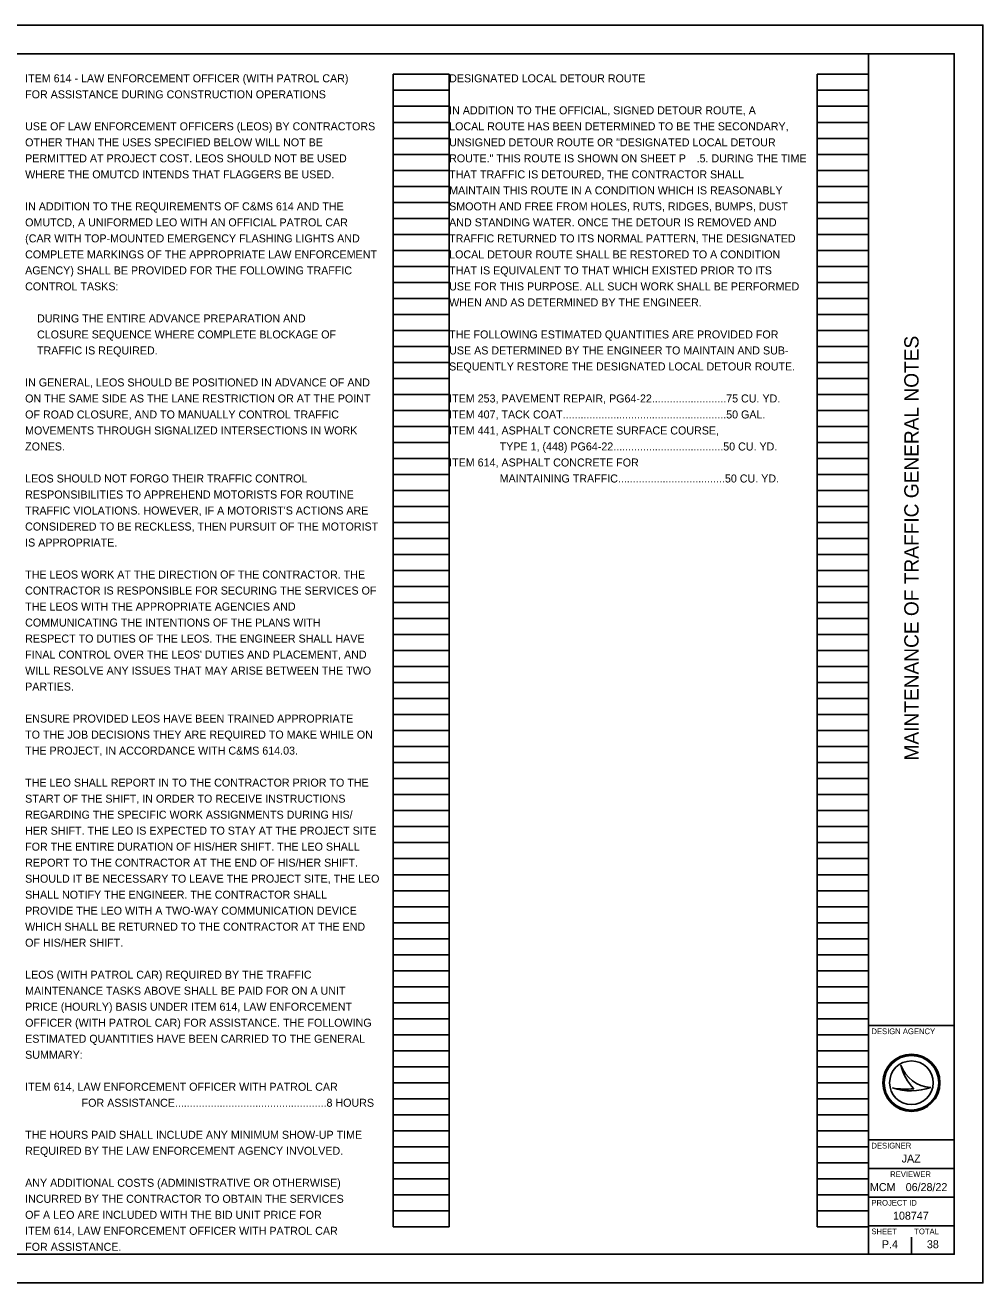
# Model space of a CAD drawing. Extents: x 0 to 34, y 0 to 22.
# Drawn here: x 17.24 to 34, y 0 to 22 of the extents above; entities that cross this region are included whole.
import ezdxf

# ---------------------------------------------------------------- set-up
doc = ezdxf.new("R2010")
doc.units = 0
for name, color, linetype in [('SH_Border', 7, 'Continuous'), ('SH_Cut_Line', 7, 'Continuous'), ('SH_Data', 7, 'Continuous'), ('SH_Text', 7, 'Continuous')]:
    doc.layers.add(name, color=color, linetype=linetype)

msp = doc.modelspace()

# ---------------------------------------------------------------- linework, layer by layer
at = {"layer": 'SH_Border'}
for p, q in [((32, 0.5), (32, 21.5)), ((32, 4.5), (33.5, 4.5)), ((32, 2.5), (33.5, 2.5)), ((32, 2), (33.5, 2)), ((32, 1.5), (33.5, 1.5)), ((32, 1), (33.5, 1))]:
    msp.add_line(p, q, dxfattribs=at)
msp.add_lwpolyline([(1.5, 21.5), (33.5, 21.5), (33.5, 0.5), (1.5, 0.5)], close=True, dxfattribs=at)
at = {"layer": 'SH_Cut_Line'}
msp.add_lwpolyline([(0, 0), (34, 0), (34, 22), (0, 22)], close=True, dxfattribs=at)
at = {"layer": 'SH_Data'}
for p, q in [((23.68, 0.98), (23.68, 21.14)), ((23.68, 21.14), (24.66, 21.14)), ((24.66, 0.98), (24.66, 21.14)), ((31.1, 0.98), (31.1, 21.14)), ((31.1, 21.14), (32, 21.14)), ((32, 0.98), (32, 21.14)), ((23.68, 20.86), (24.66, 20.86)), ((31.1, 20.86), (32, 20.86)), ((23.68, 20.58), (24.66, 20.58)), ((31.1, 20.58), (32, 20.58)), ((23.68, 20.3), (24.66, 20.3)), ((31.1, 20.3), (32, 20.3)), ((23.68, 20.02), (24.66, 20.02)), ((31.1, 20.02), (32, 20.02)), ((23.68, 19.74), (24.66, 19.74)), ((31.1, 19.74), (32, 19.74)), ((23.68, 19.46), (24.66, 19.46)), ((31.1, 19.46), (32, 19.46)), ((23.68, 19.18), (24.66, 19.18)), ((31.1, 19.18), (32, 19.18)), ((23.68, 18.9), (24.66, 18.9)), ((31.1, 18.9), (32, 18.9)), ((23.68, 18.62), (24.66, 18.62)), ((31.1, 18.62), (32, 18.62)), ((23.68, 18.34), (24.66, 18.34)), ((31.1, 18.34), (32, 18.34)), ((23.68, 18.06), (24.66, 18.06)), ((31.1, 18.06), (32, 18.06)), ((23.68, 17.78), (24.66, 17.78)), ((31.1, 17.78), (32, 17.78)), ((23.68, 17.5), (24.66, 17.5)), ((31.1, 17.5), (32, 17.5)), ((23.68, 17.22), (24.66, 17.22)), ((31.1, 17.22), (32, 17.22)), ((23.68, 16.94), (24.66, 16.94)), ((31.1, 16.94), (32, 16.94)), ((23.68, 16.66), (24.66, 16.66)), ((31.1, 16.66), (32, 16.66)), ((23.68, 16.38), (24.66, 16.38)), ((31.1, 16.38), (32, 16.38)), ((23.68, 16.1), (24.66, 16.1)), ((31.1, 16.1), (32, 16.1)), ((23.68, 15.82), (24.66, 15.82)), ((31.1, 15.82), (32, 15.82)), ((23.68, 15.54), (24.66, 15.54)), ((31.1, 15.54), (32, 15.54)), ((23.68, 15.26), (24.66, 15.26)), ((31.1, 15.26), (32, 15.26)), ((23.68, 14.98), (24.66, 14.98)), ((31.1, 14.98), (32, 14.98)), ((23.68, 14.7), (24.66, 14.7)), ((31.1, 14.7), (32, 14.7)), ((23.68, 14.42), (24.66, 14.42)), ((31.1, 14.42), (32, 14.42)), ((23.68, 14.14), (24.66, 14.14)), ((31.1, 14.14), (32, 14.14)), ((23.68, 13.86), (24.66, 13.86)), ((31.1, 13.86), (32, 13.86)), ((23.68, 13.58), (24.66, 13.58)), ((31.1, 13.58), (32, 13.58)), ((23.68, 13.3), (24.66, 13.3)), ((31.1, 13.3), (32, 13.3)), ((23.68, 13.02), (24.66, 13.02)), ((31.1, 13.02), (32, 13.02)), ((23.68, 12.74), (24.66, 12.74)), ((31.1, 12.74), (32, 12.74)), ((23.68, 12.46), (24.66, 12.46)), ((31.1, 12.46), (32, 12.46)), ((23.68, 12.18), (24.66, 12.18)), ((31.1, 12.18), (32, 12.18)), ((23.68, 11.9), (24.66, 11.9)), ((31.1, 11.9), (32, 11.9)), ((23.68, 11.62), (24.66, 11.62)), ((31.1, 11.62), (32, 11.62)), ((23.68, 11.34), (24.66, 11.34)), ((31.1, 11.34), (32, 11.34)), ((23.68, 11.06), (24.66, 11.06)), ((31.1, 11.06), (32, 11.06)), ((23.68, 10.78), (24.66, 10.78)), ((31.1, 10.78), (32, 10.78)), ((23.68, 10.5), (24.66, 10.5)), ((31.1, 10.5), (32, 10.5)), ((23.68, 10.22), (24.66, 10.22)), ((31.1, 10.22), (32, 10.22)), ((23.68, 9.94), (24.66, 9.94)), ((31.1, 9.94), (32, 9.94)), ((23.68, 9.66), (24.66, 9.66)), ((31.1, 9.66), (32, 9.66)), ((23.68, 9.38), (24.66, 9.38)), ((31.1, 9.38), (32, 9.38)), ((23.68, 9.1), (24.66, 9.1)), ((31.1, 9.1), (32, 9.1)), ((23.68, 8.82), (24.66, 8.82)), ((31.1, 8.82), (32, 8.82)), ((23.68, 8.54), (24.66, 8.54)), ((31.1, 8.54), (32, 8.54)), ((23.68, 8.26), (24.66, 8.26)), ((31.1, 8.26), (32, 8.26)), ((23.68, 7.98), (24.66, 7.98)), ((31.1, 7.98), (32, 7.98)), ((23.68, 7.7), (24.66, 7.7)), ((31.1, 7.7), (32, 7.7)), ((23.68, 7.42), (24.66, 7.42)), ((31.1, 7.42), (32, 7.42)), ((23.68, 7.14), (24.66, 7.14)), ((31.1, 7.14), (32, 7.14)), ((23.68, 6.86), (24.66, 6.86)), ((31.1, 6.86), (32, 6.86)), ((23.68, 6.58), (24.66, 6.58)), ((31.1, 6.58), (32, 6.58)), ((23.68, 6.3), (24.66, 6.3)), ((31.1, 6.3), (32, 6.3)), ((23.68, 6.02), (24.66, 6.02)), ((31.1, 6.02), (32, 6.02)), ((23.68, 5.74), (24.66, 5.74)), ((31.1, 5.74), (32, 5.74)), ((23.68, 5.46), (24.66, 5.46)), ((31.1, 5.46), (32, 5.46)), ((23.68, 5.18), (24.66, 5.18)), ((31.1, 5.18), (32, 5.18)), ((23.68, 4.9), (24.66, 4.9)), ((31.1, 4.9), (32, 4.9)), ((23.68, 4.62), (24.66, 4.62)), ((31.1, 4.62), (32, 4.62)), ((23.68, 4.34), (24.66, 4.34)), ((31.1, 4.34), (32, 4.34)), ((23.68, 4.06), (24.66, 4.06)), ((31.1, 4.06), (32, 4.06)), ((23.68, 3.78), (24.66, 3.78)), ((31.1, 3.78), (32, 3.78)), ((32.567, 3.81), (32.567, 3.81)), ((23.68, 3.5), (24.66, 3.5)), ((31.1, 3.5), (32, 3.5)), ((32.417, 3.41), (32.417, 3.41)), ((32.75, 3.5), (32.75, 3.5)), ((33.087, 3.419), (33.087, 3.419)), ((23.68, 3.22), (24.66, 3.22)), ((31.1, 3.22), (32, 3.22)), ((23.68, 2.94), (24.66, 2.94)), ((31.1, 2.94), (32, 2.94)), ((23.68, 2.66), (24.66, 2.66)), ((31.1, 2.66), (32, 2.66)), ((23.68, 2.38), (24.66, 2.38)), ((31.1, 2.38), (32, 2.38)), ((23.68, 2.1), (24.66, 2.1)), ((31.1, 2.1), (32, 2.1)), ((23.68, 1.82), (24.66, 1.82)), ((31.1, 1.82), (32, 1.82)), ((23.68, 1.54), (24.66, 1.54)), ((31.1, 1.54), (32, 1.54)), ((23.68, 1.26), (24.66, 1.26)), ((31.1, 1.26), (32, 1.26)), ((23.68, 0.98), (24.66, 0.98)), ((31.1, 0.98), (32, 0.98)), ((32.375, 0.675), (32.375, 0.675)), ((32.75, 0.5), (32.75, 0.8))]:
    msp.add_line(p, q, dxfattribs=at)
for radius in [0.5, 0.477, 0.477, 0.382]:
    msp.add_circle((32.75, 3.5), radius, dxfattribs=at)
for centre, radius, start, end in [((33.116, 3.998), 0.58, 198.9257, 198.9319), ((33.347, 3.97), 0.796, 191.6379, 191.6421), ((33.116, 3.998), 0.58, 198.9319, 267.1657), ((33.347, 3.97), 0.796, 191.6421, 226.0947), ((32.739, 4.37), 1.013, 251.4576, 290.0832), ((32.648, 4.654), 1.266, 259.4964, 259.4995), ((32.739, 4.37), 1.013, 251.4527, 251.4576), ((32.648, 4.654), 1.266, 259.4995, 276.6672)]:
    msp.add_arc(centre, radius, start, end, dxfattribs=at)

# ---------------------------------------------------------------- texts
msp.add_text('MAINTENANCE OF TRAFFIC GENERAL NOTES', height=0.25, rotation=90, dxfattribs=at).set_placement((32.875, 9.137))
for s, height, p in [('DESIGN AGENCY', 0.1, (32.05, 4.35)), ('DESIGNER', 0.1, (32.05, 2.35)), ('JAZ', 0.14, (32.579, 2.105)), ('REVIEWER', 0.1, (32.378, 1.85)), ('MCM', 0.14, (32.024, 1.605)), ('06/28/22', 0.14, (32.65, 1.605)), ('PROJECT ID', 0.1, (32.05, 1.35)), ('108747', 0.14, (32.428, 1.105)), ('SHEET', 0.1, (32.05, 0.85)), ('TOTAL', 0.1, (32.8, 0.85)), ('P.4', 0.14, (32.233, 0.605)), ('38', 0.14, (33.021, 0.605))]:
    msp.add_text(s, height=height, dxfattribs=at).set_placement(p)
at = {"layer": 'SH_Text'}
for s, p in [('ITEM 614 - LAW ENFORCEMENT OFFICER (WITH PATROL CAR)', (17.24, 21)), ('DESIGNATED LOCAL DETOUR ROUTE', (24.66, 21)), ('FOR ASSISTANCE DURING CONSTRUCTION OPERATIONS', (17.24, 20.72)), ('IN ADDITION TO THE OFFICIAL, SIGNED DETOUR ROUTE, A', (24.66, 20.44)), ('USE OF LAW ENFORCEMENT OFFICERS (LEOS) BY CONTRACTORS', (17.24, 20.16)), ('LOCAL ROUTE HAS BEEN DETERMINED TO BE THE SECONDARY,', (24.66, 20.16)), ('OTHER THAN THE USES SPECIFIED BELOW WILL NOT BE', (17.24, 19.88)), ('UNSIGNED DETOUR ROUTE OR "DESIGNATED LOCAL DETOUR', (24.66, 19.88)), ('PERMITTED AT PROJECT COST. LEOS SHOULD NOT BE USED', (17.24, 19.6)), ('ROUTE." THIS ROUTE IS SHOWN ON SHEET P', (24.66, 19.6)), ('.5. DURING THE TIME', (28.99, 19.6)), ('WHERE THE OMUTCD INTENDS THAT FLAGGERS BE USED.', (17.24, 19.32)), ('THAT TRAFFIC IS DETOURED, THE CONTRACTOR SHALL', (24.66, 19.32)), ('MAINTAIN THIS ROUTE IN A CONDITION WHICH IS REASONABLY', (24.66, 19.04)), ('IN ADDITION TO THE REQUIREMENTS OF C&MS 614 AND THE', (17.24, 18.76)), ('SMOOTH AND FREE FROM HOLES, RUTS, RIDGES, BUMPS, DUST', (24.66, 18.76)), ('OMUTCD, A UNIFORMED LEO WITH AN OFFICIAL PATROL CAR', (17.24, 18.48)), ('AND STANDING WATER. ONCE THE DETOUR IS REMOVED AND', (24.66, 18.48)), ('(CAR WITH TOP-MOUNTED EMERGENCY FLASHING LIGHTS AND', (17.24, 18.2)), ('TRAFFIC RETURNED TO ITS NORMAL PATTERN, THE DESIGNATED', (24.66, 18.2)), ('COMPLETE MARKINGS OF THE APPROPRIATE LAW ENFORCEMENT', (17.24, 17.92)), ('LOCAL DETOUR ROUTE SHALL BE RESTORED TO A CONDITION', (24.66, 17.92)), ('AGENCY) SHALL BE PROVIDED FOR THE FOLLOWING TRAFFIC', (17.24, 17.64)), ('THAT IS EQUIVALENT TO THAT WHICH EXISTED PRIOR TO ITS', (24.66, 17.64)), ('CONTROL TASKS:', (17.24, 17.36)), ('USE FOR THIS PURPOSE. ALL SUCH WORK SHALL BE PERFORMED', (24.66, 17.36)), ('WHEN AND AS DETERMINED BY THE ENGINEER.', (24.66, 17.08)), ('    DURING THE ENTIRE ADVANCE PREPARATION AND', (17.24, 16.8)), ('    CLOSURE SEQUENCE WHERE COMPLETE BLOCKAGE OF', (17.24, 16.52)), ('THE FOLLOWING ESTIMATED QUANTITIES ARE PROVIDED FOR', (24.66, 16.52)), ('    TRAFFIC IS REQUIRED.', (17.24, 16.24)), ('USE AS DETERMINED BY THE ENGINEER TO MAINTAIN AND SUB-', (24.66, 16.24)), ('SEQUENTLY RESTORE THE DESIGNATED LOCAL DETOUR ROUTE.', (24.66, 15.96)), ('IN GENERAL, LEOS SHOULD BE POSITIONED IN ADVANCE OF AND', (17.24, 15.68)), ('ON THE SAME SIDE AS THE LANE RESTRICTION OR AT THE POINT', (17.24, 15.4)), ('ITEM 253, PAVEMENT REPAIR, PG64-22.........................75 CU. YD.', (24.66, 15.4)), ('OF ROAD CLOSURE, AND TO MANUALLY CONTROL TRAFFIC', (17.24, 15.12)), ('ITEM 407, TACK COAT.......................................................50 GAL.', (24.66, 15.12)), ('MOVEMENTS THROUGH SIGNALIZED INTERSECTIONS IN WORK', (17.24, 14.84)), ('ITEM 441, ASPHALT CONCRETE SURFACE COURSE,', (24.66, 14.84)), ('ZONES.', (17.24, 14.56)), ('                 TYPE 1, (448) PG64-22.....................................50 CU. YD.', (24.66, 14.56)), ('ITEM 614, ASPHALT CONCRETE FOR', (24.66, 14.28)), ('LEOS SHOULD NOT FORGO THEIR TRAFFIC CONTROL', (17.24, 14)), ('                 MAINTAINING TRAFFIC....................................50 CU. YD.', (24.66, 14)), ('RESPONSIBILITIES TO APPREHEND MOTORISTS FOR ROUTINE', (17.24, 13.72)), ("TRAFFIC VIOLATIONS. HOWEVER, IF A MOTORIST'S ACTIONS ARE", (17.24, 13.44)), ('CONSIDERED TO BE RECKLESS, THEN PURSUIT OF THE MOTORIST', (17.24, 13.16)), ('IS APPROPRIATE.', (17.24, 12.88)), ('THE LEOS WORK AT THE DIRECTION OF THE CONTRACTOR. THE', (17.24, 12.32)), ('CONTRACTOR IS RESPONSIBLE FOR SECURING THE SERVICES OF', (17.24, 12.04)), ('THE LEOS WITH THE APPROPRIATE AGENCIES AND', (17.24, 11.76)), ('COMMUNICATING THE INTENTIONS OF THE PLANS WITH', (17.24, 11.48)), ('RESPECT TO DUTIES OF THE LEOS. THE ENGINEER SHALL HAVE', (17.24, 11.2)), ("FINAL CONTROL OVER THE LEOS' DUTIES AND PLACEMENT, AND", (17.24, 10.92)), ('WILL RESOLVE ANY ISSUES THAT MAY ARISE BETWEEN THE TWO', (17.24, 10.64)), ('PARTIES.', (17.24, 10.36)), ('ENSURE PROVIDED LEOS HAVE BEEN TRAINED APPROPRIATE', (17.24, 9.8)), ('TO THE JOB DECISIONS THEY ARE REQUIRED TO MAKE WHILE ON', (17.24, 9.52)), ('THE PROJECT, IN ACCORDANCE WITH C&MS 614.03.', (17.24, 9.24)), ('THE LEO SHALL REPORT IN TO THE CONTRACTOR PRIOR TO THE', (17.24, 8.68)), ('START OF THE SHIFT, IN ORDER TO RECEIVE INSTRUCTIONS', (17.24, 8.4)), ('REGARDING THE SPECIFIC WORK ASSIGNMENTS DURING HIS/', (17.24, 8.12)), ('HER SHIFT. THE LEO IS EXPECTED TO STAY AT THE PROJECT SITE', (17.24, 7.84)), ('FOR THE ENTIRE DURATION OF HIS/HER SHIFT. THE LEO SHALL', (17.24, 7.56)), ('REPORT TO THE CONTRACTOR AT THE END OF HIS/HER SHIFT.', (17.24, 7.28)), ('SHOULD IT BE NECESSARY TO LEAVE THE PROJECT SITE, THE LEO', (17.24, 7)), ('SHALL NOTIFY THE ENGINEER. THE CONTRACTOR SHALL', (17.24, 6.72)), ('PROVIDE THE LEO WITH A TWO-WAY COMMUNICATION DEVICE', (17.24, 6.44)), ('WHICH SHALL BE RETURNED TO THE CONTRACTOR AT THE END', (17.24, 6.16)), ('OF HIS/HER SHIFT.', (17.24, 5.88)), ('LEOS (WITH PATROL CAR) REQUIRED BY THE TRAFFIC', (17.24, 5.32)), ('MAINTENANCE TASKS ABOVE SHALL BE PAID FOR ON A UNIT', (17.24, 5.04)), ('PRICE (HOURLY) BASIS UNDER ITEM 614, LAW ENFORCEMENT', (17.24, 4.76)), ('OFFICER (WITH PATROL CAR) FOR ASSISTANCE. THE FOLLOWING', (17.24, 4.48)), ('ESTIMATED QUANTITIES HAVE BEEN CARRIED TO THE GENERAL', (17.24, 4.2)), ('SUMMARY:', (17.24, 3.92)), ('ITEM 614, LAW ENFORCEMENT OFFICER WITH PATROL CAR', (17.24, 3.36)), ('                   FOR ASSISTANCE...................................................8 HOURS', (17.24, 3.08)), ('THE HOURS PAID SHALL INCLUDE ANY MINIMUM SHOW-UP TIME', (17.24, 2.52)), ('REQUIRED BY THE LAW ENFORCEMENT AGENCY INVOLVED.', (17.24, 2.24)), ('ANY ADDITIONAL COSTS (ADMINISTRATIVE OR OTHERWISE)', (17.24, 1.68)), ('INCURRED BY THE CONTRACTOR TO OBTAIN THE SERVICES', (17.24, 1.4)), ('OF A LEO ARE INCLUDED WITH THE BID UNIT PRICE FOR', (17.24, 1.12)), ('ITEM 614, LAW ENFORCEMENT OFFICER WITH PATROL CAR', (17.24, 0.84)), ('FOR ASSISTANCE.', (17.24, 0.56))]:
    msp.add_text(s, height=0.14, dxfattribs=at).set_placement(p)

doc.saveas('drawing.dxf')
